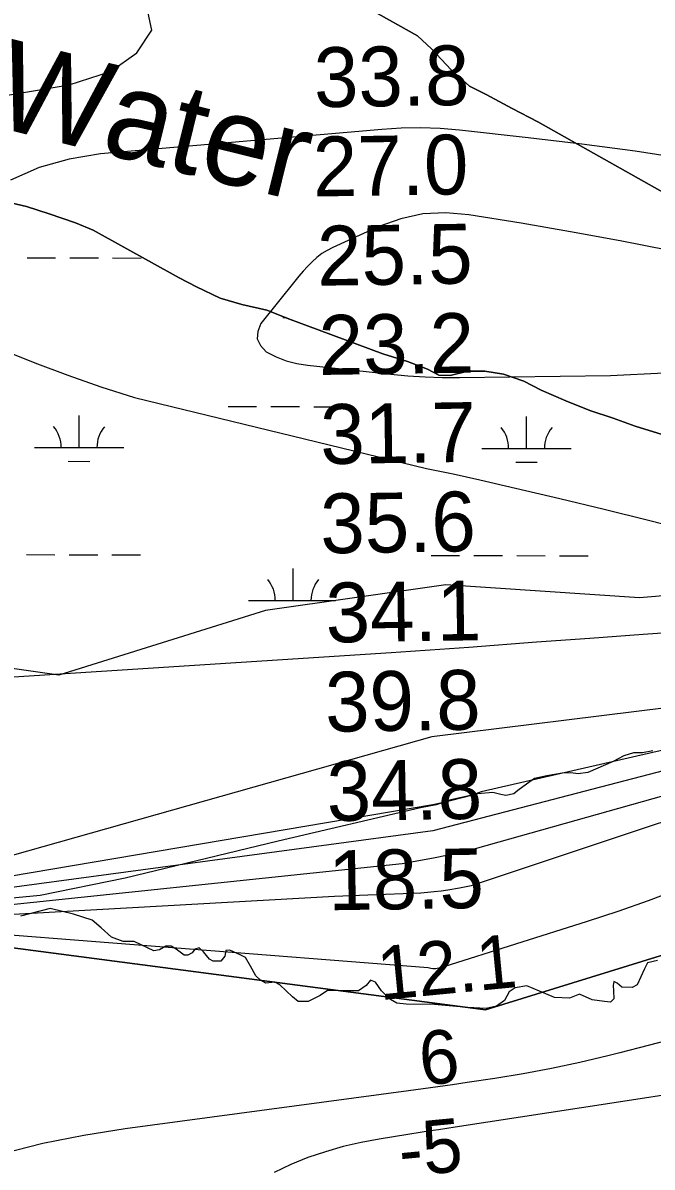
# Model space of a CAD drawing. Extents: x 3219052 to 3256913, y 800770 to 826146.
# Drawn here: x 3230928 to 3231634, y 812403 to 813685 of the extents above; entities that cross this region are included whole.
import ezdxf

# ---------------------------------------------------------------- set-up
doc = ezdxf.new("R2010")
doc.units = 0
for name, color, linetype in [('V-RIVR-EDGE', 7, 'Continuous'), ('V-RIVR-IDEN', 7, 'Continuous'), ('V-RIVR-RANG', 7, 'Continuous'), ('V-SITE-VEGE', 7, 'Continuous'), ('V-TOPO-DPTH', 7, 'Continuous'), ('V-TOPO-MAJR', 7, 'Continuous'), ('V-TOPO-MINR', 7, 'Continuous'), ('V-TOPO-SHOR', 7, 'Continuous'), ('V-TOPO-WATR', 7, 'Continuous'), ('V-WETL-SWMP', 7, 'Continuous')]:
    doc.layers.add(name, color=color, linetype=linetype)

msp = doc.modelspace()

# ---------------------------------------------------------------- linework, layer by layer
at = {"layer": 'V-RIVR-EDGE'}
for points in [[(3231347.4, 812586.4), (3231340.3, 812590.4), (3231330.4, 812600.3), (3231323.7, 812609.8), (3231317.8, 812612.2), (3231313.1, 812606.3), (3231304.3, 812600.4), (3231289.7, 812600.4), (3231279, 812600.5), (3231269.6, 812600.5), (3231261.6, 812595), (3231248.2, 812588.3), (3231236.7, 812588.3), (3231230.4, 812593.5), (3231216.2, 812606.9), (3231210.7, 812610.1), (3231200.4, 812608.9), (3231194.5, 812612.1), (3231189.3, 812616.9), (3231183.4, 812628), (3231177.9, 812637.5), (3231171.6, 812640.6), (3231160.2, 812645.8), (3231155.8, 812645.4), (3231154.6, 812639.1), (3231149.9, 812633.6), (3231141.6, 812633.6), (3231137.2, 812635.6), (3231130.5, 812643.9), (3231125.8, 812648.3), (3231121, 812647.1), (3231117.9, 812642.8), (3231113.1, 812640.4), (3231108.8, 812640.4), (3231100.1, 812646.8), (3231094.5, 812650.3), (3231088.2, 812650.3), (3231081.1, 812646.4), (3231074.8, 812645.2), (3231052.7, 812655.6), (3231040.4, 812655.6), (3231027.4, 812660.4), (3231015.9, 812670.7), (3231005.7, 812679.4), (3230984.7, 812686.2), (3230958.7, 812692.6), (3230925.4, 812684)], [(3231639.7, 812634.3), (3231628.6, 812631.6), (3231625.4, 812624.9), (3231617.1, 812607.1), (3231611.5, 812604), (3231599.7, 812604.4), (3231594.5, 812608.8), (3231591, 812610.7), (3231590.2, 812606.4), (3231590.6, 812600.1), (3231590.9, 812591.4), (3231587, 812587.4), (3231580.3, 812588.2), (3231566.4, 812590.3), (3231552.2, 812596.6), (3231541.1, 812591.9), (3231524.5, 812592.7), (3231507.5, 812599.9), (3231493.3, 812605.9), (3231480.3, 812603.5), (3231473.5, 812599.2), (3231468.4, 812589.3), (3231459.3, 812583), (3231447.8, 812580.3), (3231426.9, 812581.5), (3231389.7, 812584.8), (3231358.1, 812585.2), (3231347.4, 812586.4)]]:
    msp.add_lwpolyline(points, dxfattribs=at)
at = {"layer": 'V-SITE-VEGE'}
for points in [[(3231648.3, 813494), (3231505.5, 813574.3), (3231476.8, 813589.2), (3231447.6, 813604.7), (3231429.1, 813614.1), (3231408.3, 813632.4), (3231386.3, 813655.9), (3231370.8, 813670.7), (3231263.9, 813730.8)], [(3230903.3, 813485.9), (3230932.2, 813479.1), (3230957.6, 813471.2), (3230986.9, 813460.9), (3231006.8, 813452.8), (3231103.2, 813399.2), (3231122.8, 813389.1), (3231149.4, 813376.7), (3231173.7, 813369.6), (3231201.8, 813362.9), (3231247.2, 813345.5), (3231331.8, 813314.1), (3231359.5, 813305.6), (3231381.8, 813296.8), (3231394.7, 813290.4), (3231407.4, 813289.7), (3231427.1, 813294.6), (3231446.1, 813294.8), (3231467.1, 813291.3), (3231489.9, 813283.4), (3231509.5, 813273.6), (3231537, 813261.6), (3231563.8, 813250.7), (3231590.3, 813242), (3231614.8, 813232.9), (3231739.5, 813194.6)], [(3231634.7, 812869.2), (3231623.2, 812867), (3231612.9, 812867), (3231602.2, 812863.5), (3231590, 812857.3), (3231561.8, 812844.9), (3231551, 812843.6), (3231542.6, 812844.4), (3231532.9, 812844.1), (3231515.7, 812841.2), (3231502, 812838.4), (3231492.9, 812832), (3231483.3, 812824.7), (3231478.6, 812821.2), (3231469.9, 812819), (3231464.2, 812820.4), (3231455.3, 812822.4), (3231438.5, 812820.9), (3231408.2, 812814.3), (3231391.6, 812808.6), (3231374.1, 812805.3), (3231214.5, 812767.9), (3231042.8, 812726.4), (3230947.4, 812707.2), (3230817.9, 812694.8)]]:
    msp.add_lwpolyline(points, dxfattribs=at)
at = {"layer": 'V-TOPO-DPTH'}
for points in [[(3231853, 812858.5), (3231430.8, 812717.8), (3231417.6, 812715.3), (3231404.7, 812713.1), (3231397.1, 812712), (3231389.5, 812711.1), (3231381.9, 812710.4), (3231374.3, 812709.9), (3231314.9, 812707.6), (3231277.6, 812706), (3230817.2, 812680.2)], [(3230916.8, 812648.3), (3230948.3, 812644.2), (3231447.1, 812579.1), (3231978, 812742.9), (3232294.1, 812834.9), (3232335, 812843.9), (3232376.1, 812852.4)], [(3230916.8, 812648.3), (3230948.3, 812644.2), (3231447.1, 812579.1), (3231978, 812742.9), (3232294.1, 812834.9), (3232335, 812843.9), (3232376.1, 812852.4)], [(3231646.9, 812483.3), (3231591.3, 812474.7), (3231412.9, 812447.5), (3231403.6, 812446), (3231394.3, 812444.6), (3231385.1, 812443.2), (3231375.8, 812441.7), (3231327.7, 812434.2), (3231307.4, 812430.3), (3231287.2, 812425.7), (3231267.3, 812420), (3231247.6, 812413.4), (3231228.5, 812405.5), (3231209.9, 812396.6)], [(3231646.9, 812483.3), (3231591.3, 812474.7), (3231412.9, 812447.5), (3231403.6, 812446), (3231394.3, 812444.6), (3231385.1, 812443.2), (3231375.8, 812441.7), (3231327.7, 812434.2), (3231307.4, 812430.3), (3231287.2, 812425.7), (3231267.3, 812420), (3231247.6, 812413.4), (3231228.5, 812405.5), (3231209.9, 812396.6)]]:
    msp.add_lwpolyline(points, dxfattribs=at)
at = {"layer": 'V-TOPO-MAJR'}
for points in [[(3230512.2, 813721.9), (3230537.4, 813664.9), (3230583.7, 813616.3), (3230674.2, 813578.2), (3230754.3, 813578.1), (3230868.2, 813596.9), (3230979.9, 813615.7), (3231026.3, 813630.4), (3231055.9, 813651.4), (3231072.8, 813676.7), (3231068.4, 813696)], [(3232521.1, 813453.3), (3232077.2, 813474.8), (3232055.1, 813476), (3232033, 813477.4), (3232011, 813479.1), (3231988.9, 813480.9), (3231966.9, 813483.1), (3231944.9, 813485.7), (3231923.1, 813488.9), (3231901.2, 813492.5), (3231734.5, 813522), (3231674.7, 813531.9), (3231614.9, 813541.1), (3231554.8, 813549.1), (3231494.6, 813556.3), (3231417.7, 813564.7), (3231395.9, 813566.5), (3231374.1, 813567.4), (3231352.3, 813567), (3231330.5, 813565.7), (3231015.1, 813538.3), (3230980, 813532.4), (3230946.2, 813523.1), (3230914.2, 813508.6)], [(3230878.8, 813329.1), (3230941.4, 813304.1), (3230978.3, 813290.2), (3231015.5, 813277.1), (3231053.1, 813265.3), (3231380.8, 813185.6), (3231410.7, 813179.6), (3231440.5, 813173.1), (3231480.7, 813163.7), (3231530.4, 813151.9), (3231580.2, 813139.9), (3231629.8, 813127.6), (3231679.4, 813114.9)], [(3232448.8, 812995.5), (3232214.9, 812967.9), (3232167.9, 812962.4), (3232121, 812957), (3232074, 812951.7), (3232027.1, 812946.4), (3232001.5, 812943.5), (3231967.3, 812939.6), (3231933.2, 812935.6), (3231442.2, 812823.4), (3231436.2, 812821.1), (3231430, 812819.2), (3231423.8, 812817.4), (3231404.8, 812812.6), (3231396.3, 812810.6), (3231387.7, 812808.6), (3230913.1, 812728.5)]]:
    msp.add_lwpolyline(points, dxfattribs=at)
at = {"layer": 'V-TOPO-MINR'}
for points in [[(3233184.5, 813076.9), (3232531.5, 812986.9), (3232507.2, 812984.4), (3232482.9, 812981.9), (3232458.6, 812979.2), (3232351, 812967.3), (3232281.3, 812959.5), (3232211.5, 812951.6), (3232141.8, 812943.4), (3232072.1, 812935.2), (3231983.7, 812924.6), (3231958.2, 812921.4), (3231932.8, 812918.2), (3231907.4, 812914.8), (3231387.8, 812779.6), (3230809.7, 812702), (3230779.3, 812709.3), (3230101.2, 813088.9), (3230021.5, 813099.4), (3229968.4, 813124.6), (3229860.7, 813203), (3229323.9, 813555.5)], [(3231653.1, 813429.8), (3231597.8, 813440.6), (3231542.4, 813450.7), (3231486.9, 813460.4), (3231428.1, 813470.1), (3231402.3, 813472.1), (3231376.8, 813471), (3231351.9, 813465.4), (3231327.4, 813456.9), (3231275.8, 813433.4), (3231269.5, 813430.1), (3231263.4, 813426.4), (3231257.7, 813422), (3231252.4, 813417.2), (3231247.3, 813412), (3231242.4, 813406.7), (3231237.7, 813401.2), (3231233, 813395.7), (3231195, 813348.2), (3231191.4, 813339.2), (3231190.7, 813330.9), (3231194.4, 813323.3), (3231201.1, 813316.4), (3231212.1, 813310.9), (3231223.4, 813306.4), (3231235.3, 813303.4), (3231247.4, 813301.3), (3231340.8, 813291.3), (3231360, 813289.6), (3231379.3, 813288.4), (3231398.5, 813287.8), (3231417.8, 813287.7), (3231587.2, 813289.8), (3231647.5, 813292.9)], [(3233216.2, 813061.5), (3232538.3, 812970.9), (3232522.2, 812969.5), (3232506.1, 812968), (3232489.9, 812966.5), (3232473.8, 812964.9), (3232403.4, 812957.6), (3232352.1, 812952.1), (3232300.8, 812946.4), (3232249.6, 812940.2), (3232198.4, 812933.8), (3231964.4, 812903.6), (3231948.4, 812901.5), (3231932.4, 812899.3), (3231423.5, 812756), (3231388.5, 812748.8), (3231353.3, 812742.7), (3230839.9, 812688.7), (3230816.3, 812691.5), (3230801.6, 812694.5), (3230086.4, 813075.4), (3230022.9, 813080.2), (3229961, 813108.3), (3229772.2, 813238.6)], [(3230847.6, 812947.5), (3231341.1, 812979.4), (3231362.9, 812980.8), (3231384.7, 812982.3), (3231406.5, 812983.8), (3231428.2, 812985.5), (3231504.2, 812991.2), (3231563.9, 812995.6), (3231623.7, 813000), (3231683.4, 813004.2), (3231743.2, 813008.3), (3231889.1, 813018.1), (3231912, 813019.8), (3231934.9, 813021.8), (3231957.7, 813024.1), (3231980.6, 813026.6), (3232427.5, 813130.3)], [(3233197.5, 813105.8), (3232558, 813027.7), (3232552.8, 813026.8), (3232547.6, 813026), (3232533.9, 813024.5), (3232521.8, 813023.1), (3232509.7, 813021.7), (3232497.6, 813020.2), (3232485.5, 813018.7), (3232076.9, 812967.9), (3232053.1, 812965), (3232029.2, 812962.2), (3232005.3, 812959.5), (3231981.3, 812957), (3231948.5, 812953.6), (3231941, 812952.8), (3231933.5, 812952), (3231925.9, 812951.2), (3231918.4, 812950.5), (3231386.8, 812884.8), (3230858.7, 812735.8)], [(3231853, 812858.5), (3231430.8, 812717.8), (3231417.6, 812715.3), (3231404.7, 812713.1), (3231397.1, 812712), (3231389.5, 812711.1), (3231381.9, 812710.4), (3231374.3, 812709.9), (3231314.9, 812707.6), (3231277.6, 812706), (3230817.2, 812680.2)], [(3231663.2, 812713.8), (3231629.4, 812701.1), (3231595.2, 812689.2), (3231560.9, 812677.8), (3231400.1, 812627), (3231398.4, 812626.5), (3231396.5, 812626), (3231392.9, 812625.2), (3231391.1, 812625), (3231387.9, 812625.1), (3231385.5, 812625.4), (3231382.5, 812626.1), (3230808.7, 812670.7)], [(3231661.2, 812547.2), (3231629.4, 812538.9), (3231597.6, 812530.8), (3231584.1, 812527.4), (3231552.7, 812520), (3231521.1, 812513.2), (3231489.3, 812507.4), (3231457.4, 812502.2), (3231426.4, 812497.5), (3231409.9, 812495.1), (3231393.5, 812492.8), (3231377, 812490.5), (3231360.5, 812488.2), (3231042.7, 812445.7), (3230996.4, 812438.3), (3230950.4, 812429.2), (3230905, 812417.6)], [(3231646.9, 812483.3), (3231591.3, 812474.7), (3231412.9, 812447.5), (3231403.6, 812446), (3231394.3, 812444.6), (3231385.1, 812443.2), (3231375.8, 812441.7), (3231327.7, 812434.2), (3231307.4, 812430.3), (3231287.2, 812425.7), (3231267.3, 812420), (3231247.6, 812413.4), (3231228.5, 812405.5), (3231209.9, 812396.6)]]:
    msp.add_lwpolyline(points, dxfattribs=at)
at = {"layer": 'V-TOPO-SHOR'}
for points in [[(3231263.9, 813730.8), (3231370.8, 813670.7), (3231386.3, 813655.9), (3231408.3, 813632.4), (3231429.1, 813614.1), (3231447.6, 813604.7), (3231476.8, 813589.2), (3231505.5, 813574.3), (3231648.3, 813494)], [(3231739.5, 813194.6), (3231614.8, 813232.9), (3231590.3, 813242), (3231563.8, 813250.7), (3231537, 813261.6), (3231509.5, 813273.6), (3231489.9, 813283.4), (3231467.1, 813291.3), (3231446.1, 813294.8), (3231427.1, 813294.6), (3231407.4, 813289.7), (3231394.7, 813290.4), (3231381.8, 813296.8), (3231359.5, 813305.6), (3231331.8, 813314.1), (3231247.2, 813345.5), (3231227.1, 813353.1), (3231201.8, 813362.9), (3231173.7, 813369.6), (3231149.4, 813376.7), (3231122.8, 813389.1), (3231103.2, 813399.2), (3231006.8, 813452.8), (3230986.9, 813460.9), (3230957.6, 813471.2), (3230932.2, 813479.1), (3230903.3, 813485.9)]]:
    msp.add_lwpolyline(points, dxfattribs=at)
at = {"layer": 'V-TOPO-WATR'}
msp.add_lwpolyline([(3232376.1, 812852.4), (3232335, 812843.9), (3232294.1, 812834.9), (3231978, 812742.9), (3231447.1, 812579.1), (3230948.3, 812644.2), (3230916.8, 812648.3)], dxfattribs=at)
at = {"layer": 'V-WETL-SWMP'}
for p, q in [((3230932.7, 813421.8), (3230964.7, 813421.7)), ((3230980.7, 813421.7), (3231012.7, 813421.6)), ((3231028.7, 813421.6), (3231060.7, 813421.5)), ((3231219.8, 813355), (3231222.2, 813355)), ((3231158.2, 813255.1), (3231190.2, 813255.1)), ((3231206.2, 813255), (3231238.2, 813255)), ((3231254.2, 813254.9), (3231286.2, 813254.9)), ((3230991.1, 813209.1), (3230991.1, 813245.1)), ((3231493, 813208), (3231493, 813244)), ((3230941.1, 813209.2), (3231041.1, 813209)), ((3231443, 813208.1), (3231543, 813207.9)), ((3230979, 813193.7), (3231003, 813193.6)), ((3231480.9, 813192.6), (3231504.9, 813192.6)), ((3230932, 813089.1), (3230964, 813089)), ((3230980, 813089), (3231012, 813088.9)), ((3231028, 813088.9), (3231060, 813088.8)), ((3231385.9, 813088.2), (3231417.9, 813088.1)), ((3231433.9, 813088.1), (3231465.9, 813088)), ((3231481.9, 813088), (3231513.9, 813087.9)), ((3231529.9, 813087.9), (3231561.9, 813087.8)), ((3231231.2, 813037.7), (3231231.3, 813073.7)), ((3231181.2, 813037.8), (3231278.8, 813037.6))]:
    msp.add_line(p, q, dxfattribs=at)
for points in [[(3231648.3, 813494), (3231505.5, 813574.3), (3231476.8, 813589.2), (3231447.6, 813604.7), (3231429.1, 813614.1), (3231408.3, 813632.4), (3231386.3, 813655.9), (3231370.8, 813670.7), (3231263.9, 813730.8)], [(3232922, 813243.6), (3232748.3, 813214.6), (3232560.2, 813171.2), (3232343.1, 813127.7), (3232184, 813098.8), (3231966.9, 813084.3), (3231793.3, 813055.3), (3231619.6, 813040.8), (3231402.6, 813055.3), (3231200, 813026.4), (3230968.4, 812953.9), (3230765.8, 812982.9), (3230563.3, 813055.3), (3230433, 813171.2), (3230259.4, 813287.1), (3230071.3, 813316), (3229810.8, 813460.9), (3229764.4, 813512.4)], [(3230903.3, 813485.9), (3230932.2, 813479.1), (3230957.6, 813471.2), (3230986.9, 813460.9), (3231006.8, 813452.8), (3231103.2, 813399.2), (3231122.8, 813389.1), (3231149.4, 813376.7), (3231173.7, 813369.6), (3231201.8, 813362.9), (3231227.1, 813353.1), (3231247.2, 813345.5), (3231331.8, 813314.1), (3231359.5, 813305.6), (3231381.8, 813296.8), (3231394.7, 813290.4), (3231407.4, 813289.7), (3231427.1, 813294.6), (3231446.1, 813294.8), (3231467.1, 813291.3), (3231489.9, 813283.4), (3231509.5, 813273.6), (3231537, 813261.6), (3231563.8, 813250.7), (3231590.3, 813242), (3231614.8, 813232.9), (3231739.5, 813194.6)]]:
    msp.add_lwpolyline(points, dxfattribs=at)
for centre, start, end in [((3230935.8, 813209.7), 359.1081, 40.6518), ((3231046.3, 813209.4), 139.1081, 180.6517), ((3231437.7, 813208.6), 359.1081, 40.6518), ((3231548.2, 813208.4), 139.1081, 180.6517), ((3231175.9, 813038.3), 359.1081, 40.6518), ((3231286.4, 813038.1), 139.1081, 180.6517)]:
    msp.add_arc(centre, 35.2, start, end, dxfattribs=at)

# ---------------------------------------------------------------- texts
at = {"layer": 'V-RIVR-IDEN'}
msp.add_text('Water', height=100, rotation=346.139, dxfattribs=at).set_placement((3230890.9, 813570.2))
at = {"layer": 'V-RIVR-RANG'}
for s, height, rotation, p in [('33.8', 67, 0.8883, (3231255, 813590.4)), ('27.0', 67, 0.8883, (3231253.8, 813490.4)), ('25.5', 67, 0.8883, (3231258.5, 813390.4)), ('23.2', 67, 0.8883, (3231260.3, 813290.4)), ('31.7', 67, 0.8883, (3231262.1, 813190.5)), ('35.6', 67, 0.8883, (3231262.1, 813090.4)), ('34.1', 67, 0.8883, (3231268.1, 812990.5)), ('39.8', 67, 0.8883, (3231267.5, 812890.5)), ('34.8', 67, 0.8883, (3231269.3, 812790.5)), ('18.5', 67, 0.8883, (3231271.1, 812690.5)), ('12.1', 60, 5.5051, (3231328.6, 812589.7)), ('6', 60, 5.5051, (3231375.3, 812494.1)), ('-5', 60, 5.5051, (3231352.2, 812391.7))]:
    msp.add_text(s, height=height, rotation=rotation, dxfattribs=at).set_placement(p)

doc.saveas('drawing.dxf')
